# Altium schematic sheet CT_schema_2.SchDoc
size 461 x 327 mm
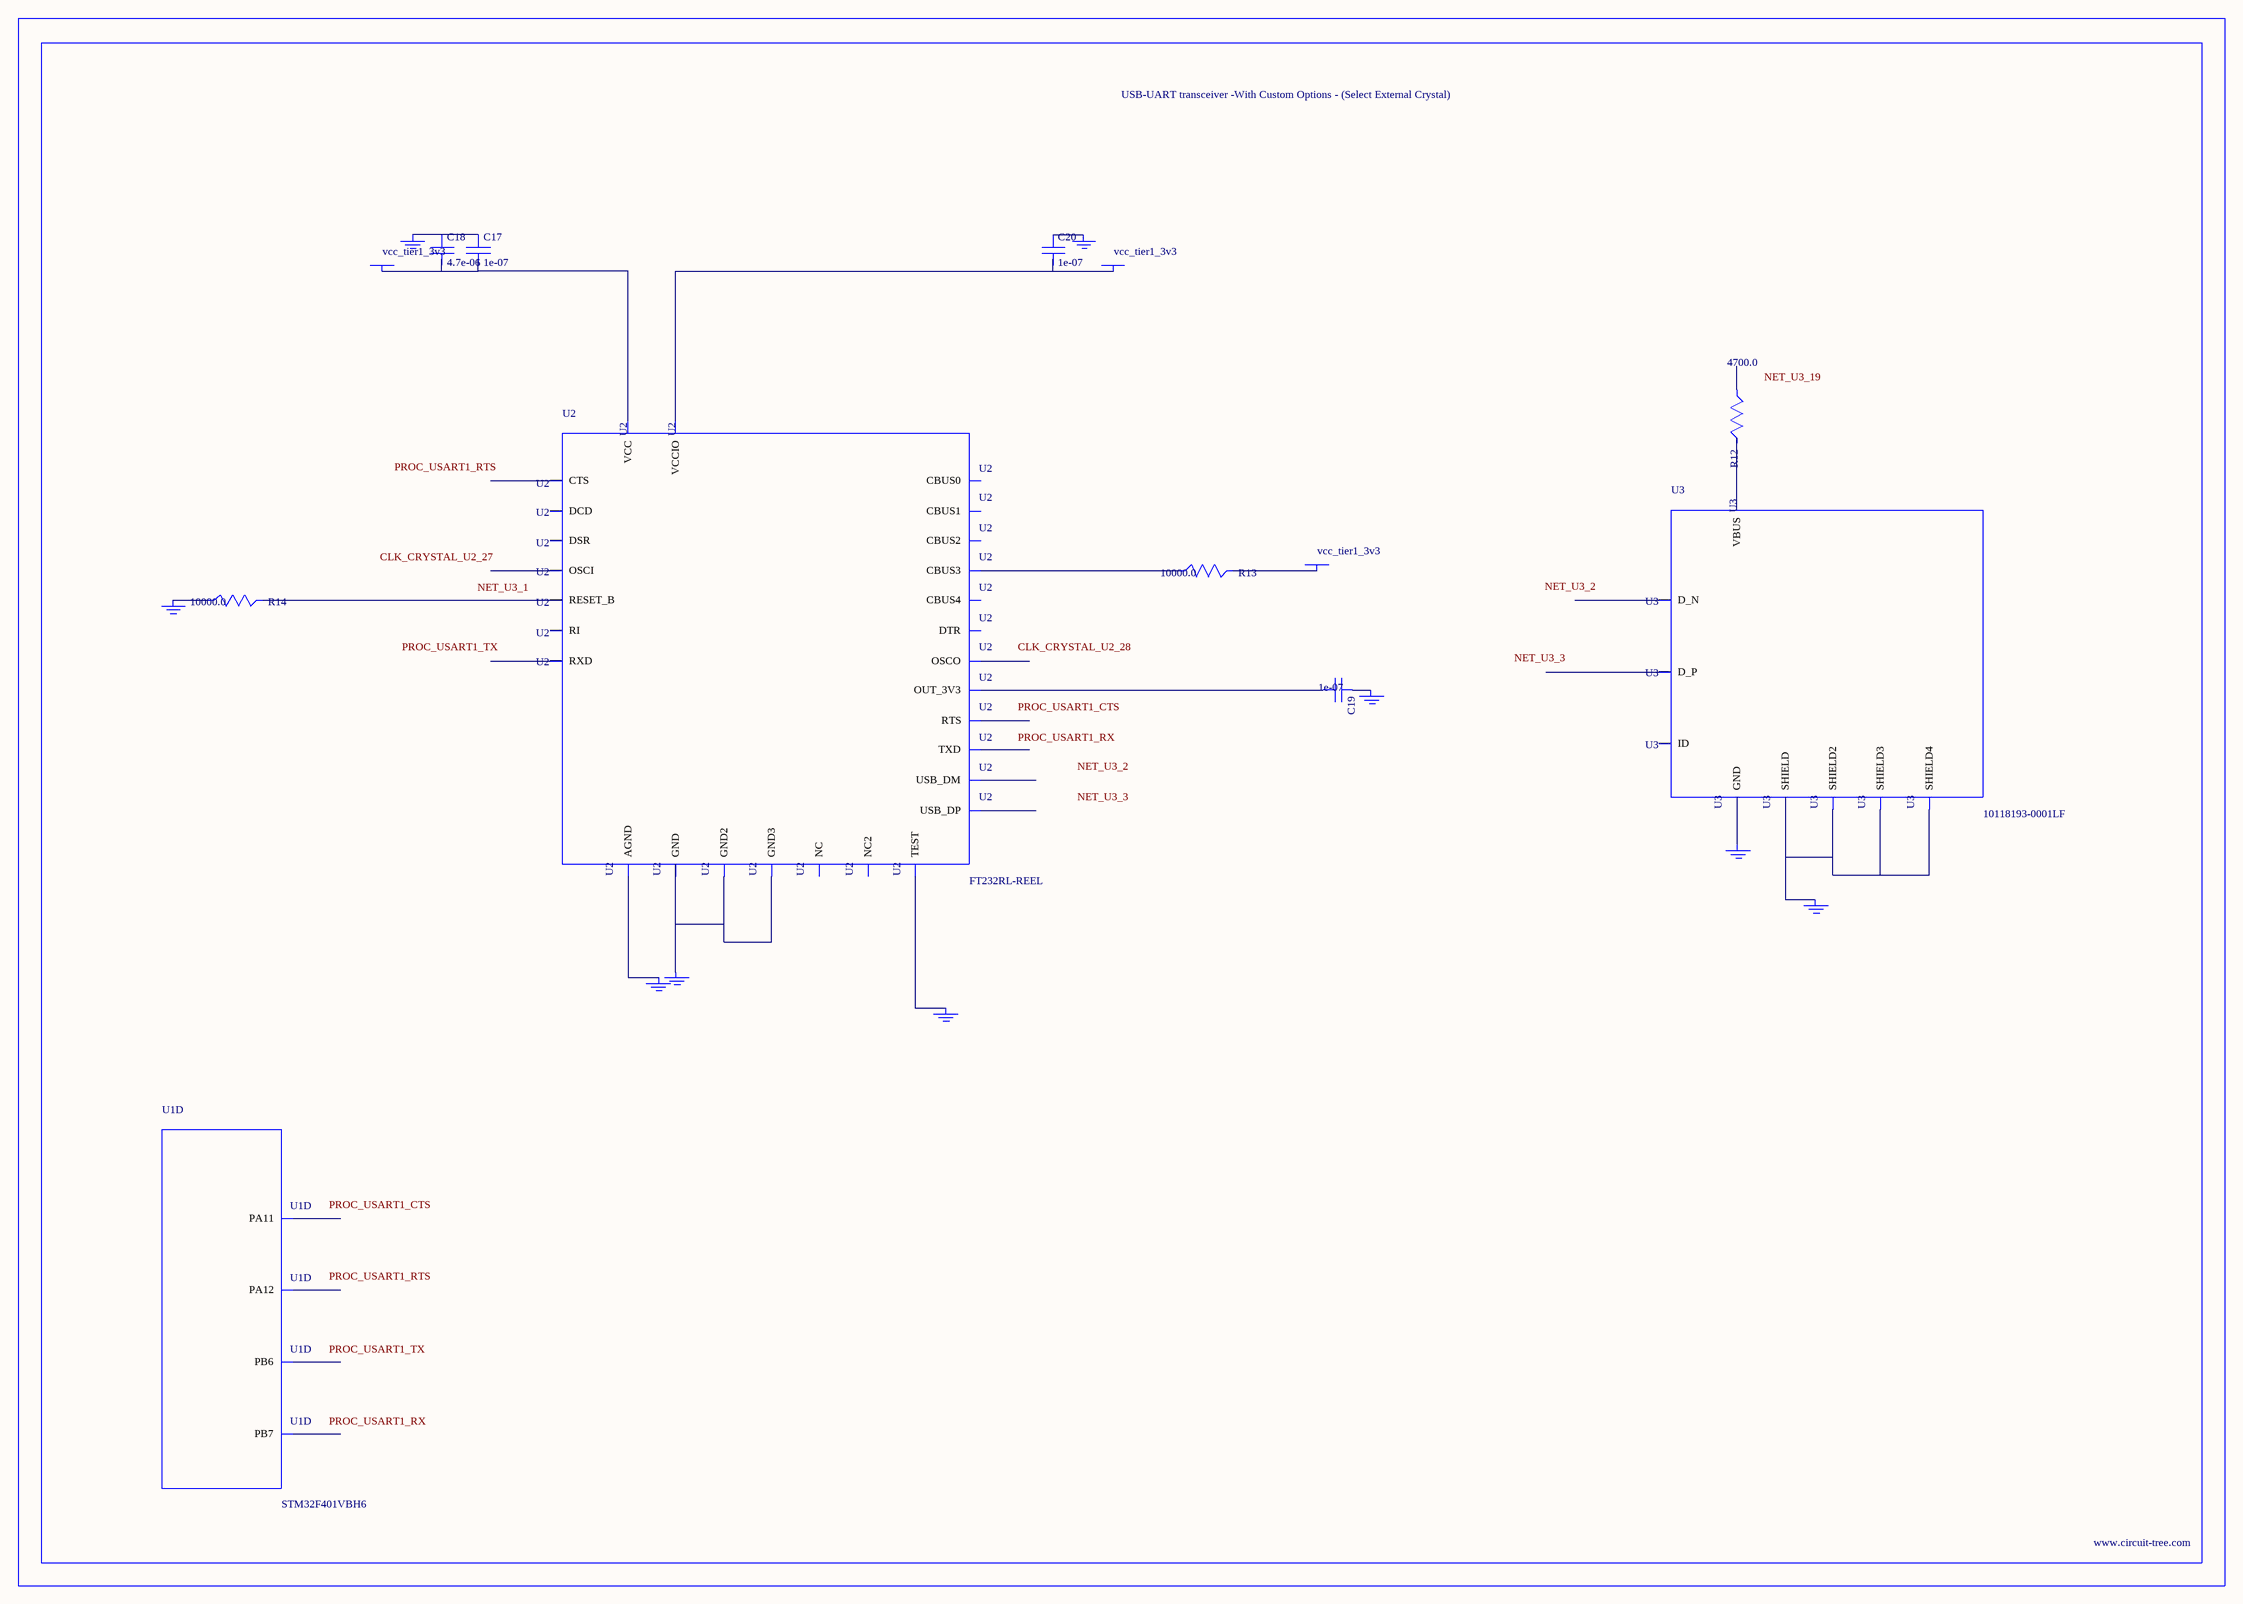
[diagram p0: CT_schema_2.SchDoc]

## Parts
BORDER1  (no value)
C17  1e-07  [C0402]
C18  4.7e-06  [C0805]
C19  1e-07  [C0402]
C20  1e-07  [C0402]
GND_INSTANCE_1_0  (no value)
GND_INSTANCE_1_1  (no value)
GND_INSTANCE_1_2  (no value)
GND_INSTANCE_1_3  (no value)
GND_INSTANCE_1_4  (no value)
GND_INSTANCE_1_5  (no value)
GND_INSTANCE_1_6  (no value)
GND_INSTANCE_1_7  (no value)
GND_INSTANCE_1_8  (no value)
POWER_INSTANCE_1_0  vcc_tier1_3v3
POWER_INSTANCE_1_1  vcc_tier1_3v3
POWER_INSTANCE_1_2  vcc_tier1_3v3
R12  4700.0  [R0603]
R13  10000.0  [R0603]
R14  10000.0  [R0603]
U1  STM32F401VBH6  [UFBGA100]  (part D of 8)
U2  FT232RL-REEL  [SSOP-28]
U3  10118193-0001LF  [FCI_10118193-0001LF]

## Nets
NetC17_1: C17.1 C18.1 GND_INSTANCE_1_3.0(GND)
NetC17_2: C17.2 C18.2 POWER_INSTANCE_1_2.0(PWR) U2.20(VCC)
NetC19_1: C19.1 GND_INSTANCE_1_1.0(GND)
NetC19_2: C19.2 U2.17(OUT_3V3)
NetC20_1: C20.1 GND_INSTANCE_1_0.0(GND)
NetC20_2: C20.2 POWER_INSTANCE_1_0.0(PWR) U2.4(VCCIO)
NetGND_INSTANCE_1_2_0: GND_INSTANCE_1_2.0(GND) R14.1
NetGND_INSTANCE_1_4_0: GND_INSTANCE_1_4.0(GND) U2.25(AGND)
NetGND_INSTANCE_1_5_0: GND_INSTANCE_1_5.0(GND) U2.26(TEST)
NetGND_INSTANCE_1_6_0: GND_INSTANCE_1_6.0(GND) U2.7(GND) U2.18(GND2) U2.21(GND3)
NetGND_INSTANCE_1_7_0: GND_INSTANCE_1_7.0(GND) U3.6(SHIELD) U3.7(SHIELD2) U3.8(SHIELD3) U3.9(SHIELD4)
NetGND_INSTANCE_1_8_0: GND_INSTANCE_1_8.0(GND) U3.5(GND)
NetPOWER_INSTANCE_1_1_0: POWER_INSTANCE_1_1.0(PWR) R13.2
NetR12_2: R12.2 U3.1(VBUS)
NetR13_1: R13.1 U2.14(CBUS3)
NetR14_2: R14.2 U2.19(RESET_B)

Not connected (* = marked no-connect by the designer): R12 1; U1 A12(PA12) B4(PB7) B5(PB6) B12(PA11); U2 1(TXD) 2(DTR) 3(RTS) 5(RXD) 6(RI) 8(NC) 9(DSR) 10(DCD) 11(CTS) 12(CBUS4) 13(CBUS2) 15(USB_DP) 16(USB_DM) 22(CBUS1) 23(CBUS0) 24(NC2) 27(OSCI) 28(OSCO); U3 2(D_N) 3(D_P) 4(ID)

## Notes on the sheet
- Labels drawn without touching a wire or pin: CLK_CRYSTAL_U2_27, CLK_CRYSTAL_U2_28, NET_U3_1, NET_U3_2, NET_U3_3, NET_U3_19, PROC_USART1_CTS, PROC_USART1_RTS, PROC_USART1_RX, PROC_USART1_TX

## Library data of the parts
BORDER1 = BORDER_PAGE1
C17 C19 C20 = C0402C104K3RACTU
C18 = C0805C475K4RACTU
GND_INSTANCE_1_0-GND_INSTANCE_1_8 = GND
POWER_INSTANCE_1_0-POWER_INSTANCE_1_2 = PWR
R12 = RC0603JR-074K7L
R13 R14 = RC0603JR-0710KL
